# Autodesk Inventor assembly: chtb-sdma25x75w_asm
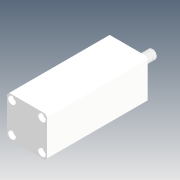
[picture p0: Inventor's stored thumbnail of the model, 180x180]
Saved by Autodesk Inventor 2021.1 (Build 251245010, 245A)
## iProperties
Company: Microsoft
Created: 2018-05
Part Number: chtb-sdma25x75w_asm
Description: STEP AP214
Document SubType Name: Assembly
Designer: user
Title: chtb-sdma25x75w_asm.STEP
Author: Windows
Revision Number: ÈÎºÎ
Sending System: SolidWorks 2015
Preprocessor: SwSTEP 2.0
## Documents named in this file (4)
- D:\Vault_2016\Projekty\Clamptek\Hydraulic\CHTB\CHTB-25\Inventor\chtb-sdma25x75w\chtb-sdma25x75w_asm.iam
- D:\Vault_2016\Projekty\Clamptek\Hydraulic\CHTB\CHTB-25\Inventor\chtb-sdma25x75w\CHTB-25QG.ipt
- D:\Vault_2016\Projekty\Clamptek\Hydraulic\CHTB\CHTB-25\Inventor\chtb-sdma25x75w\CHTB-SDMA25X75NBT.ipt
- D:\Vault_2016\Projekty\Clamptek\Hydraulic\CHTB\CHTB-25\Inventor\chtb-sdma25x75w\CHTB-SDMA25X75WHSG.ipt
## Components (3 placed, 3 different names)
1. CHTB-25QG_1
2. CHTB-SDMA25X75NBT_2
3. CHTB-SDMA25X75WHSG_3
